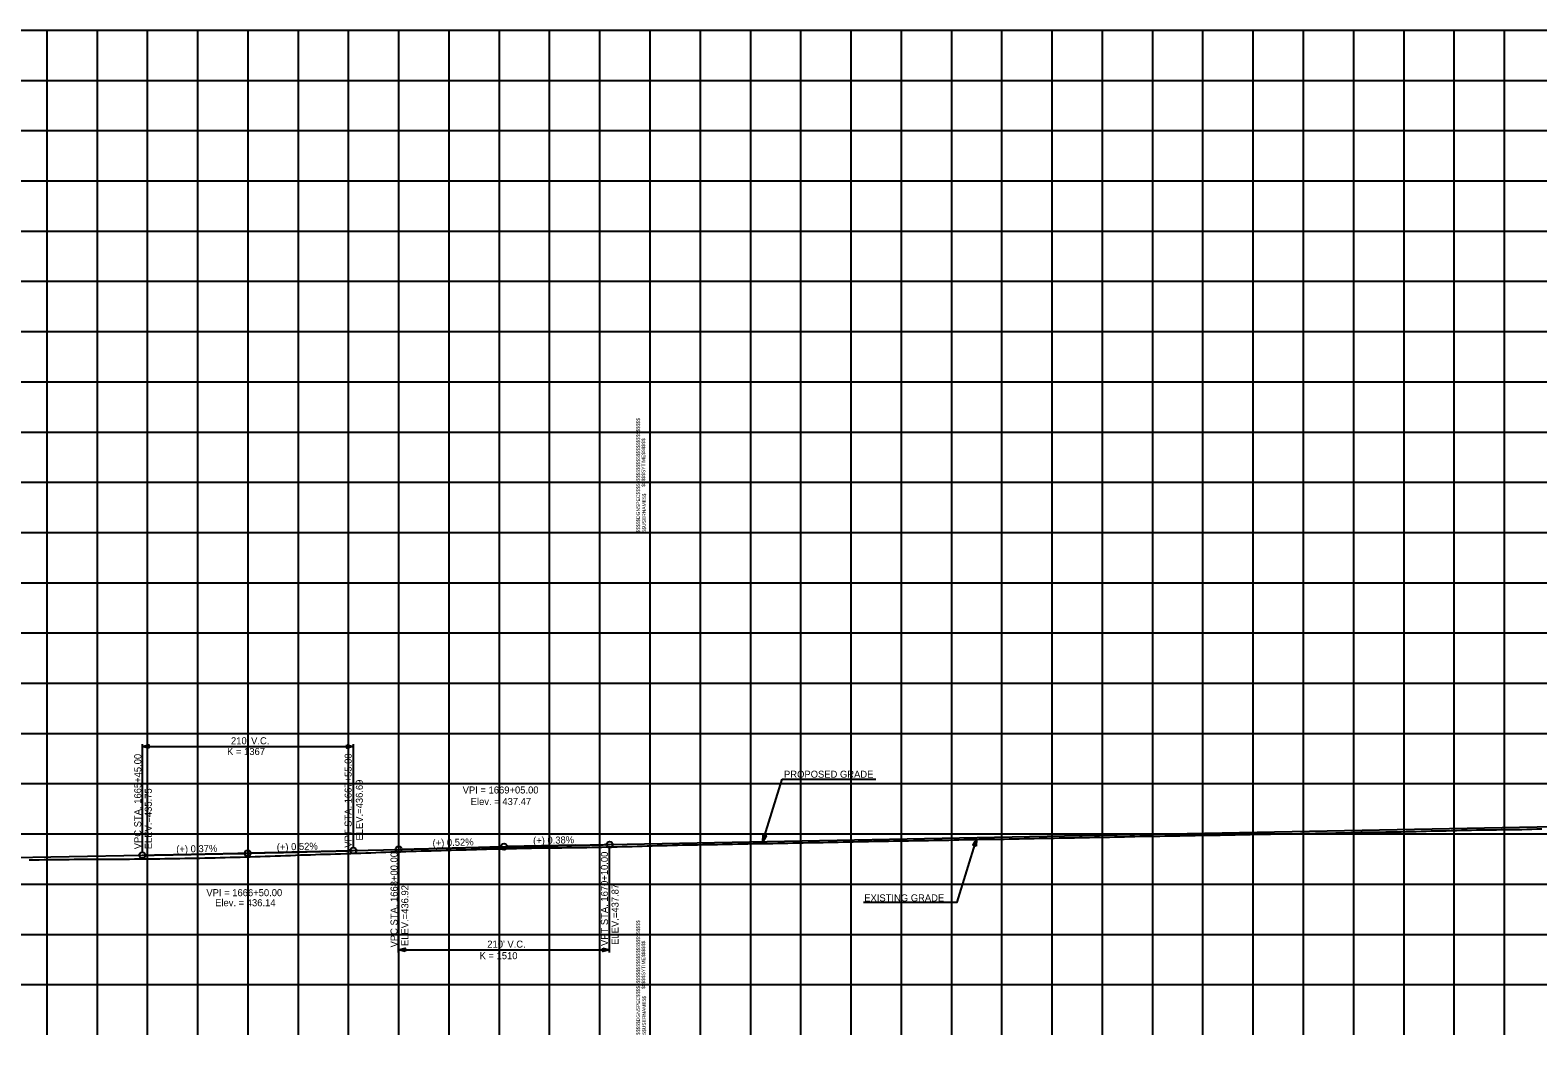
# Model space of a CAD drawing. Extents: x -90830 to 2015517, y -20856 to 836331.
# Drawn here: x 55357 to 56857, y -9797 to -8797 of the extents above; entities that cross this region are included whole.
import ezdxf

# ---------------------------------------------------------------- set-up
doc = ezdxf.new("R2010")
doc.units = 0
for name, color, linetype in [('Level 1', 7, 'Continuous'), ('RD_DDB_GradeTX', 7, 'Continuous'), ('RD_DDB_Profile_EX', 7, 'Continuous'), ('RD_DDB_Profile_Lbl', 7, 'Continuous'), ('RD_DDB_Profile_PR', 7, 'Continuous'), ('RD_DDB_StripGrade', 7, 'Continuous'), ('RD_DDB_VCLbl', 7, 'Continuous'), ('RD_PD_Final_TX', 7, 'Continuous')]:
    doc.layers.add(name, color=color, linetype=linetype)

msp = doc.modelspace()

# ---------------------------------------------------------------- linework, layer by layer
at = {"layer": 'Level 1'}
for p, q in [((54373.5, -8797.1), (55973.5, -8797.1)), ((55373.5, -8797.1), (55373.5, -9297.1)), ((55423.5, -8797.1), (55423.5, -9297.1)), ((55473.5, -8797.1), (55473.5, -9297.1)), ((55523.5, -8797.1), (55523.5, -9297.1)), ((55573.5, -8797.1), (55573.5, -9297.1)), ((55623.5, -8797.1), (55623.5, -9297.1)), ((55673.5, -8797.1), (55673.5, -9297.1)), ((55723.5, -8797.1), (55723.5, -9297.1)), ((55773.5, -8797.1), (55773.5, -9297.1)), ((55823.5, -8797.1), (55823.5, -9297.1)), ((55873.5, -8797.1), (55873.5, -9297.1)), ((55923.5, -8797.1), (55923.5, -9297.1)), ((55973.5, -8797.1), (55973.5, -9297.1)), ((55973.5, -8797.1), (55973.5, -9297.1)), ((55973.5, -8797.1), (57573.5, -8797.1)), ((55973.5, -8797.1), (55973.5, -9297.1)), ((56023.5, -8797.1), (56023.5, -9297.1)), ((56073.5, -8797.1), (56073.5, -9297.1)), ((56123.5, -8797.1), (56123.5, -9297.1)), ((56173.5, -8797.1), (56173.5, -9297.1)), ((56223.5, -8797.1), (56223.5, -9297.1)), ((56273.5, -8797.1), (56273.5, -9297.1)), ((56323.5, -8797.1), (56323.5, -9297.1)), ((56373.5, -8797.1), (56373.5, -9297.1)), ((56423.5, -8797.1), (56423.5, -9297.1)), ((56473.5, -8797.1), (56473.5, -9297.1)), ((56523.5, -8797.1), (56523.5, -9297.1)), ((56573.5, -8797.1), (56573.5, -9297.1)), ((56623.5, -8797.1), (56623.5, -9297.1)), ((56673.5, -8797.1), (56673.5, -9297.1)), ((56723.5, -8797.1), (56723.5, -9297.1)), ((56773.5, -8797.1), (56773.5, -9297.1)), ((56823.5, -8797.1), (56823.5, -9297.1)), ((54373.5, -8847.1), (55973.5, -8847.1)), ((55973.5, -8847.1), (57573.5, -8847.1)), ((54373.5, -8897.1), (55973.5, -8897.1)), ((55973.5, -8897.1), (57573.5, -8897.1)), ((54373.5, -8947.1), (55973.5, -8947.1)), ((55973.5, -8947.1), (57573.5, -8947.1)), ((54373.5, -8997.1), (55973.5, -8997.1)), ((55973.5, -8997.1), (57573.5, -8997.1)), ((54373.5, -9047.1), (55973.5, -9047.1)), ((55973.5, -9047.1), (57573.5, -9047.1)), ((54373.5, -9097.1), (55973.5, -9097.1)), ((55973.5, -9097.1), (57573.5, -9097.1)), ((54373.5, -9147.1), (55973.5, -9147.1)), ((55973.5, -9147.1), (57573.5, -9147.1)), ((54373.5, -9197.1), (55973.5, -9197.1)), ((55973.5, -9197.1), (57573.5, -9197.1)), ((54373.5, -9247.1), (55973.5, -9247.1)), ((55973.5, -9247.1), (57573.5, -9247.1)), ((54373.5, -9297.1), (55973.5, -9297.1)), ((54373.5, -9297.1), (55973.5, -9297.1)), ((55373.5, -9297.1), (55373.5, -9797.1)), ((55423.5, -9297.1), (55423.5, -9797.1)), ((55473.5, -9297.1), (55473.5, -9797.1)), ((55523.5, -9297.1), (55523.5, -9797.1)), ((55573.5, -9297.1), (55573.5, -9797.1)), ((55623.5, -9297.1), (55623.5, -9797.1)), ((55673.5, -9297.1), (55673.5, -9797.1)), ((55723.5, -9297.1), (55723.5, -9797.1)), ((55773.5, -9297.1), (55773.5, -9797.1)), ((55823.5, -9297.1), (55823.5, -9797.1)), ((55873.5, -9297.1), (55873.5, -9797.1)), ((55923.5, -9297.1), (55923.5, -9797.1)), ((55973.5, -9297.1), (57573.5, -9297.1)), ((55973.5, -9297.1), (55973.5, -9797.1)), ((55973.5, -9297.1), (55973.5, -9797.1)), ((55973.5, -9297.1), (57573.5, -9297.1)), ((55973.5, -9297.1), (55973.5, -9797.1)), ((56023.5, -9297.1), (56023.5, -9797.1)), ((56073.5, -9297.1), (56073.5, -9797.1)), ((56123.5, -9297.1), (56123.5, -9797.1)), ((56173.5, -9297.1), (56173.5, -9797.1)), ((56223.5, -9297.1), (56223.5, -9797.1)), ((56273.5, -9297.1), (56273.5, -9797.1)), ((56323.5, -9297.1), (56323.5, -9797.1)), ((56373.5, -9297.1), (56373.5, -9797.1)), ((56423.5, -9297.1), (56423.5, -9797.1)), ((56473.5, -9297.1), (56473.5, -9797.1)), ((56523.5, -9297.1), (56523.5, -9797.1)), ((56573.5, -9297.1), (56573.5, -9797.1)), ((56623.5, -9297.1), (56623.5, -9797.1)), ((56673.5, -9297.1), (56673.5, -9797.1)), ((56723.5, -9297.1), (56723.5, -9797.1)), ((56773.5, -9297.1), (56773.5, -9797.1)), ((56823.5, -9297.1), (56823.5, -9797.1)), ((54373.5, -9347.1), (55973.5, -9347.1)), ((55973.5, -9347.1), (57573.5, -9347.1)), ((54373.5, -9397.1), (55973.5, -9397.1)), ((55973.5, -9397.1), (57573.5, -9397.1)), ((54373.5, -9447.1), (55973.5, -9447.1)), ((55973.5, -9447.1), (57573.5, -9447.1)), ((54373.5, -9497.1), (55973.5, -9497.1)), ((55973.5, -9497.1), (57573.5, -9497.1)), ((54373.5, -9547.1), (55973.5, -9547.1)), ((55973.5, -9547.1), (57573.5, -9547.1)), ((54373.5, -9597.1), (55973.5, -9597.1)), ((55973.5, -9597.1), (57573.5, -9597.1)), ((54373.5, -9647.1), (55973.5, -9647.1)), ((55973.5, -9647.1), (57573.5, -9647.1)), ((54373.5, -9697.1), (55973.5, -9697.1)), ((55973.5, -9697.1), (57573.5, -9697.1)), ((54373.5, -9747.1), (55973.5, -9747.1)), ((55973.5, -9747.1), (57573.5, -9747.1))]:
    msp.add_line(p, q, dxfattribs=at)
at = {"layer": 'RD_DDB_GradeTX'}
for p, q in [((55644.4, -9614.6), (55576.5, -9616.3)), ((55757.5, -9611.6), (55825.5, -9609.8)), ((55899.4, -9608.4), (55831.5, -9609.7)), ((55502.5, -9617.7), (55570.5, -9616.5))]:
    msp.add_line(p, q, dxfattribs=at)
for centre in [(55573.5, -9616.4), (55828.5, -9609.8)]:
    msp.add_circle(centre, 3, dxfattribs=at)
at = {"layer": 'RD_DDB_Profile_EX'}
for points in [[(56420.9, -9600.4), (56425.9, -9600.3), (56430.9, -9600.2), (56435.9, -9600.1), (56440.9, -9600), (56445.9, -9599.9), (56450.9, -9599.8), (56455.9, -9599.7), (56460.9, -9599.5), (56465.9, -9599.4), (56470.9, -9599.4), (56475.9, -9599.3), (56480.9, -9599.2), (56485.9, -9599.1), (56490.9, -9599), (56495.9, -9598.9), (56500.9, -9598.9), (56505.9, -9598.8), (56510.9, -9598.7), (56515.9, -9598.6), (56520.9, -9598.5), (56525.9, -9598.4), (56530.9, -9598.3), (56535.9, -9598.2), (56540.9, -9598.2), (56545.9, -9598.1), (56550.9, -9598), (56555.9, -9597.9), (56560.9, -9597.8), (56565.9, -9597.7), (56570.9, -9597.6), (56575.9, -9597.5), (56580.9, -9597.5), (56585.9, -9597.4), (56590.9, -9597.3), (56595.9, -9597.2), (56600.9, -9597.2), (56605.9, -9597.1), (56610.9, -9597), (56615.9, -9596.9), (56620.9, -9596.8), (56625.9, -9596.7), (56630.9, -9596.6), (56635.9, -9596.5), (56640.9, -9596.5), (56645.9, -9596.4), (56650.9, -9596.3), (56655.9, -9596.2), (56660.9, -9596.1), (56665.9, -9595.9), (56670.9, -9595.8), (56675.9, -9595.6), (56680.9, -9595.5), (56685.9, -9595.4), (56690.9, -9595.4), (56695.9, -9595.3), (56700.9, -9595.3), (56705.9, -9595.2), (56710.9, -9595.1), (56715.9, -9595), (56720.9, -9594.9), (56725.9, -9594.8), (56730.9, -9594.7), (56735.9, -9594.6), (56740.9, -9594.5), (56745.9, -9594.4), (56750.9, -9594.2), (56755.9, -9594.1), (56760.9, -9594), (56765.9, -9593.9), (56770.9, -9593.8), (56775.9, -9593.6), (56780.9, -9593.5), (56785.9, -9593.4), (56790.9, -9593.3), (56795.9, -9593.2), (56800.9, -9593.1), (56805.9, -9593), (56810.9, -9592.9), (56815.9, -9592.9), (56820.9, -9592.8), (56825.9, -9592.8), (56830.9, -9592.7), (56835.9, -9592.7), (56840.9, -9592.6), (56845.9, -9592.5), (56850.9, -9592.4), (56855.9, -9592.2), (56860.9, -9592.1)], [(55420.9, -9622.3), (55425.9, -9622.2), (55430.9, -9622.2), (55435.9, -9622.2), (55440.9, -9622.2), (55445.9, -9622.2), (55450.9, -9622.1), (55455.9, -9622.1), (55460.9, -9622), (55465.9, -9622), (55470.9, -9621.9), (55475.9, -9621.9), (55480.9, -9621.8), (55485.9, -9621.8), (55490.9, -9621.7), (55495.9, -9621.7), (55500.9, -9621.6), (55505.9, -9621.5), (55510.9, -9621.4), (55515.9, -9621.3), (55520.9, -9621.3), (55525.9, -9621.2), (55530.9, -9621), (55535.9, -9620.9), (55540.9, -9620.8), (55545.9, -9620.7), (55550.9, -9620.5), (55555.9, -9620.4), (55560.9, -9620.3), (55565.9, -9620.1), (55570.9, -9620), (55575.9, -9619.8), (55580.9, -9619.6), (55585.9, -9619.5), (55590.9, -9619.3), (55595.9, -9619.1), (55600.9, -9619), (55605.9, -9618.8), (55610.9, -9618.6), (55615.9, -9618.5), (55620.9, -9618.3), (55625.9, -9618.1), (55630.9, -9617.9), (55635.9, -9617.8), (55640.9, -9617.6), (55645.9, -9617.4), (55650.9, -9617.3), (55655.9, -9617.2), (55660.9, -9617), (55665.9, -9616.9), (55670.9, -9616.7), (55675.9, -9616.5), (55680.9, -9616.4), (55685.9, -9616.2), (55690.9, -9616), (55695.9, -9615.8), (55700.9, -9615.6), (55705.9, -9615.4), (55710.9, -9615.2), (55715.9, -9615.1), (55720.9, -9614.9), (55725.9, -9614.7), (55730.9, -9614.6), (55735.9, -9614.4), (55740.9, -9614.3), (55745.9, -9614.1), (55750.9, -9614), (55755.9, -9613.9), (55760.9, -9613.7), (55765.9, -9613.6), (55770.9, -9613.4), (55775.9, -9613.3), (55780.9, -9613.1), (55785.9, -9612.9), (55790.9, -9612.8), (55795.9, -9612.6), (55800.9, -9612.5), (55805.9, -9612.3), (55810.9, -9612.2), (55815.9, -9612.1), (55820.9, -9611.9), (55825.9, -9611.8), (55830.9, -9611.7), (55835.9, -9611.6), (55840.9, -9611.5), (55845.9, -9611.4), (55850.9, -9611.3), (55855.9, -9611.2), (55860.9, -9611.1), (55865.9, -9611.1), (55870.9, -9611), (55875.9, -9611), (55880.9, -9610.9), (55885.9, -9610.9), (55890.9, -9610.8), (55895.9, -9610.8), (55900.9, -9610.7), (55905.9, -9610.7), (55910.9, -9610.6), (55915.9, -9610.4), (55920.9, -9610.3)], [(55920.9, -9610.3), (55925.9, -9610.2), (55930.9, -9610.1), (55935.9, -9610), (55940.9, -9609.9), (55945.9, -9609.8), (55950.9, -9609.6), (55955.9, -9609.5), (55960.9, -9609.3), (55965.9, -9609.2), (55970.9, -9609), (55975.9, -9608.9), (55980.9, -9608.7), (55985.9, -9608.6), (55990.9, -9608.5), (55995.9, -9608.3), (56000.9, -9608.2), (56005.9, -9608.1), (56010.9, -9608), (56015.9, -9607.9), (56020.9, -9607.9), (56025.9, -9607.8), (56030.9, -9607.7), (56035.9, -9607.6), (56040.9, -9607.5), (56045.9, -9607.4), (56050.9, -9607.3), (56055.9, -9607.2), (56060.9, -9607.1), (56065.9, -9607), (56070.9, -9606.9), (56075.9, -9606.8), (56080.9, -9606.7), (56085.9, -9606.6), (56090.9, -9606.5), (56095.9, -9606.5), (56100.9, -9606.4), (56105.9, -9606.3), (56110.9, -9606.2), (56115.9, -9606.1), (56120.9, -9606), (56125.9, -9605.9), (56130.9, -9605.8), (56135.9, -9605.7), (56140.9, -9605.6), (56145.9, -9605.5), (56150.9, -9605.4), (56155.9, -9605.3), (56160.9, -9605.2), (56165.9, -9605.1), (56170.9, -9605), (56175.9, -9604.9), (56180.9, -9604.8), (56185.9, -9604.7), (56190.9, -9604.6), (56195.9, -9604.5), (56200.9, -9604.5), (56205.9, -9604.4), (56210.9, -9604.3), (56215.9, -9604.1), (56220.9, -9604), (56225.9, -9603.9), (56230.9, -9603.9), (56235.9, -9603.8), (56240.9, -9603.8), (56245.9, -9603.7), (56250.9, -9603.6), (56255.9, -9603.5), (56260.9, -9603.4), (56265.9, -9603.3), (56270.9, -9603.2), (56275.9, -9603), (56280.9, -9602.9), (56285.9, -9602.8), (56290.9, -9602.7), (56295.9, -9602.6), (56300.9, -9602.5), (56305.9, -9602.4), (56310.9, -9602.4), (56315.9, -9602.3), (56320.9, -9602.2), (56325.9, -9602.2), (56330.9, -9602.1), (56335.9, -9602), (56340.9, -9601.9), (56345.9, -9601.8), (56350.9, -9601.7), (56355.9, -9601.6), (56360.9, -9601.5), (56365.9, -9601.4), (56370.9, -9601.3), (56375.9, -9601.2), (56380.9, -9601.1), (56385.9, -9601), (56390.9, -9601), (56395.9, -9600.9), (56400.9, -9600.8), (56405.9, -9600.7), (56410.9, -9600.6), (56415.9, -9600.5), (56420.9, -9600.4)], [(55355.9, -9622.9), (55360.9, -9622.8), (55365.9, -9622.8), (55370.9, -9622.7), (55375.9, -9622.6), (55380.9, -9622.6), (55385.9, -9622.5), (55390.9, -9622.5), (55395.9, -9622.5), (55400.9, -9622.4), (55405.9, -9622.4), (55410.9, -9622.4), (55415.9, -9622.3), (55420.9, -9622.3)]]:
    msp.add_lwpolyline(points, dxfattribs=at)
at = {"layer": 'RD_DDB_Profile_PR'}
for p, q in [((55933.5, -9607.8), (56981.8, -9587.7)), ((55678.5, -9613.7), (55723.5, -9612.5)), ((54878.5, -9629.2), (55468.5, -9618.4))]:
    msp.add_line(p, q, dxfattribs=at)
for points in [[(55468.5, -9618.4), (55472.7, -9618.3), (55476.9, -9618.2), (55481.1, -9618.1), (55485.3, -9618), (55489.5, -9618), (55493.7, -9617.9), (55497.9, -9617.8), (55502.1, -9617.7), (55506.3, -9617.6), (55510.5, -9617.5), (55514.7, -9617.5), (55518.9, -9617.4), (55523.1, -9617.3), (55527.3, -9617.2), (55531.5, -9617.1), (55535.7, -9617), (55539.9, -9616.9), (55544.1, -9616.9), (55548.3, -9616.8), (55552.5, -9616.7), (55556.7, -9616.6), (55560.9, -9616.5), (55565.1, -9616.4), (55569.3, -9616.3), (55573.5, -9616.2), (55577.7, -9616.1), (55581.9, -9616), (55586.1, -9615.9), (55590.3, -9615.8), (55594.5, -9615.7), (55598.7, -9615.6), (55602.9, -9615.5), (55607.1, -9615.5), (55611.3, -9615.4), (55615.5, -9615.3), (55619.7, -9615.2), (55623.9, -9615.1), (55628.1, -9614.9), (55632.3, -9614.8), (55636.5, -9614.7), (55640.7, -9614.6), (55644.9, -9614.5), (55649.1, -9614.4), (55653.3, -9614.3), (55657.5, -9614.2), (55661.7, -9614.1), (55665.9, -9614), (55670.1, -9613.9), (55674.3, -9613.8), (55678.5, -9613.7)], [(55723.5, -9612.5), (55727.7, -9612.4), (55731.9, -9612.3), (55736.1, -9612.2), (55740.3, -9612.1), (55744.5, -9612), (55748.7, -9611.9), (55752.9, -9611.8), (55757.1, -9611.7), (55761.3, -9611.5), (55765.5, -9611.4), (55769.7, -9611.3), (55773.9, -9611.2), (55778.1, -9611.1), (55782.3, -9611), (55786.5, -9610.9), (55790.7, -9610.8), (55794.9, -9610.7), (55799.1, -9610.6), (55803.3, -9610.5), (55807.5, -9610.4), (55811.7, -9610.3), (55815.9, -9610.2), (55820.1, -9610.1), (55824.3, -9610), (55828.5, -9610), (55832.7, -9609.9), (55836.9, -9609.8), (55841.1, -9609.7), (55845.3, -9609.6), (55849.5, -9609.5), (55853.7, -9609.4), (55857.9, -9609.3), (55862.1, -9609.2), (55866.3, -9609.1), (55870.5, -9609), (55874.7, -9608.9), (55878.9, -9608.9), (55883.1, -9608.8), (55887.3, -9608.7), (55891.5, -9608.6), (55895.7, -9608.5), (55899.9, -9608.4), (55904.1, -9608.3), (55908.3, -9608.3), (55912.5, -9608.2), (55916.7, -9608.1), (55920.9, -9608), (55925.1, -9607.9), (55929.3, -9607.8), (55933.5, -9607.8)]]:
    msp.add_spline(points, degree=3, dxfattribs=at)
at = {"layer": 'RD_DDB_VCLbl'}
for p, q in [((55468.5, -9507.7), (55468.5, -9615.4)), ((55678.5, -9507.7), (55678.5, -9610.7)), ((55468.5, -9510.2), (55678.5, -9510.2)), ((55933.5, -9715), (55933.5, -9610.8)), ((55723.5, -9715), (55723.5, -9615.5)), ((55723.5, -9712.5), (55933.5, -9712.5))]:
    msp.add_line(p, q, dxfattribs=at)
for centre in [(55678.5, -9613.7), (55723.5, -9612.5), (55933.5, -9607.8), (55468.5, -9618.4)]:
    msp.add_circle(centre, 3, dxfattribs=at)
at = {"layer": 'RD_PD_Final_TX'}
for p, q in [((56086, -9604.8), (56105.1, -9542.5)), ((56105.1, -9542.5), (56198.5, -9542.5)), ((56086, -9604.8), (56086.4, -9598.2)), ((56087.9, -9598.7), (56086, -9604.8)), ((56086, -9604.8), (56089.5, -9599.1)), ((56086.4, -9598.2), (56089.5, -9599.1)), ((56298.4, -9602.6), (56295, -9608.3)), ((56298.1, -9609.2), (56295, -9608.3)), ((56296.6, -9608.8), (56298.4, -9602.6)), ((56298.4, -9602.6), (56298.1, -9609.2))]:
    msp.add_line(p, q, dxfattribs=at)
for points in [[(55475.1, -9511.9), (55468.5, -9510.2), (55475.1, -9508.6)], [(55671.9, -9508.6), (55678.5, -9510.2), (55671.9, -9511.9)], [(55730.1, -9714.2), (55723.5, -9712.5), (55730.1, -9710.9)], [(55926.9, -9710.9), (55933.5, -9712.5), (55926.9, -9714.2)]]:
    msp.add_lwpolyline(points, close=True, dxfattribs=at)
for points in [[(56087.8, -9598.7), (56086.1, -9604.5), (56087.8, -9598.7), (56086.1, -9604.2), (56087.8, -9598.7), (56086.1, -9604), (56087.7, -9598.7), (56086.1, -9603.8), (56087.6, -9598.6), (56086.1, -9603.4), (56087.5, -9598.6), (56086.2, -9603), (56087.4, -9598.6), (56086.2, -9602.7), (56087.4, -9598.6), (56086.2, -9602.4), (56087.3, -9598.6), (56086.2, -9602.1), (56087.3, -9598.5), (56086.2, -9601.9), (56087.2, -9598.5), (56086.3, -9601.5), (56087.1, -9598.5), (56086.3, -9601.1), (56087, -9598.4), (56086.3, -9600.8), (56086.9, -9598.4), (56086.3, -9600.3), (56086.8, -9598.4), (56086.3, -9600), (56086.8, -9598.3), (56086.4, -9599.6), (56086.7, -9598.3), (56086.4, -9599.3), (56086.6, -9598.3), (56086.4, -9599), (56086.6, -9598.3), (56086.4, -9598.6), (56086.5, -9598.3)], [(56086.2, -9604.5), (56087.9, -9598.7), (56086.3, -9604.3), (56088, -9598.8), (56086.4, -9604.1), (56088.1, -9598.8), (56086.5, -9603.9), (56088.1, -9598.8), (56086.6, -9603.7), (56088.2, -9598.8), (56086.8, -9603.5), (56088.2, -9598.8), (56086.9, -9603.3), (56088.3, -9598.8), (56087, -9603), (56088.4, -9598.9), (56087.2, -9602.8), (56088.5, -9598.8), (56087.3, -9602.5), (56088.5, -9598.9), (56087.5, -9602.3), (56088.6, -9598.9), (56087.6, -9602.1), (56088.6, -9598.9), (56087.8, -9601.7), (56088.7, -9598.9), (56088, -9601.5), (56088.7, -9598.9), (56088.2, -9601.2), (56088.8, -9599), (56088.3, -9600.9), (56088.9, -9599), (56088.5, -9600.7), (56088.9, -9599.1), (56088.6, -9600.4), (56089, -9599.1), (56088.8, -9600.1), (56089.1, -9599.1), (56088.9, -9599.9), (56089.2, -9599.1), (56089, -9599.8), (56089.3, -9599.2), (56089.4, -9599.2), (56089.3, -9599.2)], [(56186, -9664.9), (56279.4, -9664.9), (56298.4, -9602.6)], [(56298.3, -9603), (56296.5, -9608.7), (56298.2, -9603.2), (56296.5, -9608.7), (56298.1, -9603.3), (56296.4, -9608.7), (56298, -9603.5), (56296.4, -9608.6), (56297.8, -9603.7), (56296.3, -9608.6), (56297.7, -9603.9), (56296.2, -9608.6), (56297.6, -9604.1), (56296.2, -9608.6), (56297.4, -9604.4), (56296.1, -9608.6), (56297.3, -9604.6), (56296, -9608.6), (56297.2, -9604.9), (56296, -9608.5), (56297, -9605.1), (56295.9, -9608.5), (56296.8, -9605.4), (56295.9, -9608.5), (56296.6, -9605.7), (56295.8, -9608.5), (56296.5, -9605.9), (56295.7, -9608.5), (56296.3, -9606.2), (56295.7, -9608.4), (56296.2, -9606.5), (56295.6, -9608.4), (56296, -9606.8), (56295.5, -9608.3), (56295.8, -9607), (56295.5, -9608.3), (56295.7, -9607.3), (56295.4, -9608.4), (56295.6, -9607.5), (56295.3, -9608.3), (56295.4, -9607.7), (56295.2, -9608.2), (56295.1, -9608.3), (56295.2, -9608.2)], [(56296.6, -9608.7), (56298.4, -9602.9), (56296.7, -9608.8), (56298.4, -9603.2), (56296.7, -9608.7), (56298.4, -9603.4), (56296.8, -9608.8), (56298.4, -9603.7), (56296.9, -9608.8), (56298.3, -9604), (56297, -9608.8), (56298.3, -9604.4), (56297, -9608.8), (56298.3, -9604.7), (56297.1, -9608.9), (56298.3, -9605), (56297.2, -9608.8), (56298.2, -9605.3), (56297.2, -9608.9), (56298.2, -9605.6), (56297.3, -9608.9), (56298.2, -9605.9), (56297.4, -9609), (56298.2, -9606.3), (56297.5, -9609), (56298.2, -9606.6), (56297.5, -9609), (56298.2, -9607.1), (56297.6, -9609), (56298.1, -9607.5), (56297.7, -9609.1), (56298.1, -9607.8), (56297.8, -9609.1), (56298.1, -9608.1), (56297.8, -9609.1), (56298.1, -9608.4), (56297.9, -9609.1), (56298.1, -9608.8), (56298, -9609.1)]]:
    msp.add_lwpolyline(points, dxfattribs=at)

# ---------------------------------------------------------------- texts
at = {"layer": 'Level 1'}
for s, p in [('$$$$$DGNSPEC$$$$$$$$$$$$$$$$$$$$$$$$$$$$', (55963.6, -9297.2)), ('$$$$$SYTIME$$$$$$', (55968.9, -9251.6)), ('$$USERNAME$$', (55969.5, -9297)), ('$$$$$DGNSPEC$$$$$$$$$$$$$$$$$$$$$$$$$$$$', (55963.6, -9797.2)), ('$$$$$SYTIME$$$$$$', (55968.9, -9751.6)), ('$$USERNAME$$', (55969.5, -9797))]:
    msp.add_text(s, height=3.544, rotation=90, dxfattribs=at).set_placement(p)
at = {"layer": 'RD_DDB_GradeTX'}
for s, rotation, p in [('(+) 0.38%', 1.0952, (55857.4, -9607.2)), ('(+) 0.37%', 1.0536, (55502.4, -9615.7)), ('(+) 0.52%', 1.4934, (55602.4, -9613.7)), ('(+) 0.52%', 1.4934, (55757.4, -9609.6))]:
    msp.add_text(s, height=7, rotation=rotation, dxfattribs=at).set_placement(p)
at = {"layer": 'RD_DDB_Profile_Lbl'}
for s, p in [('VPI = 1669+05.00', (55787.3, -9556.9)), ('Elev. = 437.47', (55795.3, -9568.4)), ('VPI = 1666+50.00', (55532.3, -9659.1)), ('Elev. = 436.14', (55541, -9669.1))]:
    msp.add_text(s, height=7, dxfattribs=at).set_placement(p)
at = {"layer": 'RD_DDB_StripGrade'}
for s, p in [('VPC STA. 1665+45.00 ', (55467.5, -9612.4)), ('VPT STA. 1667+55.00 ', (55676.8, -9610.9)), ('ELEV.=435.75', (55478, -9612.4)), ('ELEV.=436.69', (55688, -9603.7)), ('VPC STA. 1668+00.00 ', (55722.5, -9710.1)), ('VPT STA. 1670+10.00 ', (55931.8, -9708.7)), ('ELEV.=436.92', (55733.3, -9708.7)), ('ELEV.=437.87', (55942.4, -9707.5))]:
    msp.add_text(s, height=7, rotation=90, dxfattribs=at).set_placement(p)
at = {"layer": 'RD_DDB_VCLbl'}
for s, p in [("210' V.C.", (55556.8, -9507.9)), ('K = 1367', (55552.9, -9518.6)), ("210' V.C.", (55811.8, -9710.3)), ('K = 1510', (55804.1, -9721.8))]:
    msp.add_text(s, height=7, dxfattribs=at).set_placement(p)
at = {"layer": 'RD_PD_Final_TX'}
for s, p in [('PROPOSED GRADE', (56107, -9541.2)), ('EXISTING GRADE', (56186.8, -9664.3))]:
    msp.add_text(s, height=7, dxfattribs=at).set_placement(p)

doc.saveas('drawing.dxf')
